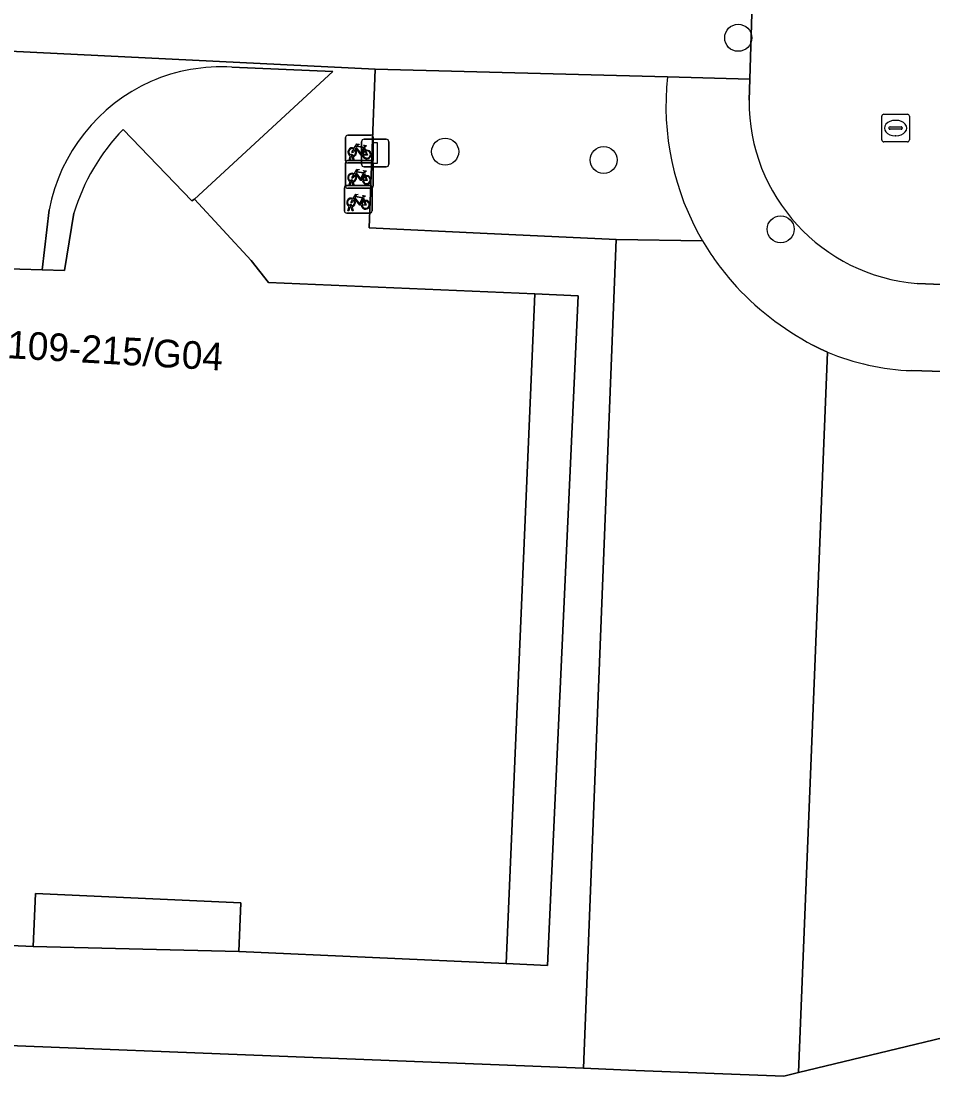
# Model space of a CAD drawing. Extents: x 161354 to 162026, y 386504 to 387460.
# Drawn here: x 161637.58 to 161670.51, y 386534.7 to 386573.47 of the extents above; entities that cross this region are included whole.
import ezdxf

# ---------------------------------------------------------------- set-up
doc = ezdxf.new("R2010")
doc.units = 0
for name, color, linetype in [('IMGEO_Boom', 7, 'Continuous'), ('IMGEO_Fietsenrek', 7, 'Continuous'), ('IMGEO_Groenvoorziening', 7, 'Continuous'), ('IMGEO_Haag', 7, 'Continuous'), ('IMGEO_Hek', 7, 'Continuous'), ('IMGEO_Lichtmast', 7, 'Continuous'), ('IMGEO_Pand', 7, 'Continuous'), ('IMGEO_Pand_nummerreeks', 7, 'Continuous'), ('IMGEO_Rijbaan_lokaal_open', 7, 'Continuous'), ('IMGEO_Rioolput', 7, 'Continuous'), ('IMGEO_Voetpad_open', 7, 'Continuous')]:
    doc.layers.add(name, color=color, linetype=linetype)

msp = doc.modelspace()

# ---------------------------------------------------------------- linework, layer by layer
at = {"layer": 'IMGEO_Boom'}
for centre in [(161663.488, 386572.878), (161652.895, 386568.761), (161658.624, 386568.459), (161665.024, 386565.954)]:
    msp.add_circle(centre, 0.489, dxfattribs=at)
at = {"layer": 'IMGEO_Fietsenrek'}
for p, q in [((161649.295, 386568.431), (161649.295, 386569.272)), ((161649.295, 386569.272), (161649.295, 386568.431)), ((161649.37, 386569.356), (161650.211, 386569.356)), ((161650.211, 386569.356), (161649.37, 386569.356)), ((161650.295, 386569.281), (161650.295, 386568.44)), ((161650.295, 386568.44), (161650.295, 386569.281)), ((161649.982, 386568.905), (161650.018, 386568.81)), ((161649.29, 386567.511), (161649.29, 386568.352)), ((161649.29, 386568.352), (161649.29, 386567.511)), ((161649.365, 386568.436), (161650.206, 386568.436)), ((161650.206, 386568.436), (161649.365, 386568.436)), ((161650.22, 386568.356), (161649.379, 386568.356)), ((161649.379, 386568.356), (161650.22, 386568.356)), ((161649.422, 386568.44), (161649.461, 386568.6)), ((161649.456, 386568.44), (161649.422, 386568.44)), ((161649.491, 386568.588), (161649.456, 386568.44)), ((161649.533, 386568.612), (161649.532, 386568.616)), ((161649.574, 386568.44), (161649.54, 386568.582)), ((161649.564, 386568.623), (161649.565, 386568.616)), ((161649.572, 386568.586), (161649.607, 386568.44)), ((161649.607, 386568.44), (161649.574, 386568.44)), ((161650.29, 386568.361), (161650.29, 386567.52)), ((161650.29, 386567.52), (161650.29, 386568.361)), ((161649.977, 386567.985), (161650.013, 386567.89)), ((161649.327, 386567.538), (161650.168, 386567.538)), ((161650.168, 386567.538), (161649.327, 386567.538)), ((161649.417, 386567.52), (161649.456, 386567.68)), ((161649.451, 386567.52), (161649.417, 386567.52)), ((161649.486, 386567.668), (161649.451, 386567.52)), ((161649.528, 386567.692), (161649.527, 386567.696)), ((161649.569, 386567.52), (161649.535, 386567.662)), ((161649.559, 386567.703), (161649.56, 386567.696)), ((161649.567, 386567.666), (161649.602, 386567.52)), ((161649.602, 386567.52), (161649.569, 386567.52)), ((161649.252, 386566.613), (161649.252, 386567.454)), ((161649.252, 386567.454), (161649.252, 386566.613)), ((161650.215, 386567.436), (161649.374, 386567.436)), ((161649.374, 386567.436), (161650.215, 386567.436)), ((161650.252, 386567.463), (161650.252, 386566.622)), ((161650.252, 386566.622), (161650.252, 386567.463)), ((161649.379, 386566.622), (161649.418, 386566.782)), ((161649.448, 386566.77), (161649.413, 386566.622)), ((161649.49, 386566.794), (161649.489, 386566.798)), ((161649.531, 386566.622), (161649.497, 386566.764)), ((161649.521, 386566.805), (161649.522, 386566.798)), ((161649.529, 386566.768), (161649.564, 386566.622)), ((161649.939, 386567.087), (161649.975, 386566.992)), ((161650.177, 386566.538), (161649.336, 386566.538)), ((161649.336, 386566.538), (161650.177, 386566.538)), ((161649.413, 386566.622), (161649.379, 386566.622)), ((161649.564, 386566.622), (161649.531, 386566.622))]:
    msp.add_line(p, q, dxfattribs=at)
for points in [[(161649.629, 386568.83), (161649.577, 386568.74), (161649.537, 386568.715), (161649.538, 386568.762), (161649.593, 386568.856)], [(161649.608, 386568.882), (161649.703, 386569.046), (161649.789, 386569.032), (161649.791, 386569.023), (161649.735, 386569.012), (161649.708, 386568.967), (161649.964, 386568.926)], [(161649.904, 386568.638), (161649.854, 386568.638), (161649.663, 386568.889), (161649.644, 386568.857)], [(161649.951, 386568.901), (161649.694, 386568.942), (161649.677, 386568.913), (161649.844, 386568.693), (161649.951, 386568.901)], [(161649.999, 386568.803), (161649.969, 386568.88), (161649.86, 386568.662), (161649.903, 386568.662)], [(161649.933, 386568.662), (161650.053, 386568.661), (161650.009, 386568.775)], [(161650.029, 386568.782), (161650.084, 386568.637), (161649.934, 386568.637)], [(161649.964, 386568.926), (161649.989, 386568.975), (161649.983, 386568.979), (161649.96, 386568.983), (161649.948, 386568.99), (161649.947, 386568.993), (161649.949, 386568.998), (161650.044, 386568.983), (161650.046, 386568.973), (161650.036, 386568.96), (161650.024, 386568.954), (161650.01, 386568.96), (161649.982, 386568.905)], [(161649.624, 386567.91), (161649.572, 386567.82), (161649.532, 386567.795), (161649.533, 386567.842), (161649.588, 386567.936)], [(161649.603, 386567.962), (161649.698, 386568.126), (161649.784, 386568.112), (161649.786, 386568.103), (161649.73, 386568.092), (161649.703, 386568.047), (161649.959, 386568.006)], [(161649.899, 386567.718), (161649.849, 386567.718), (161649.658, 386567.969), (161649.639, 386567.937)], [(161649.946, 386567.981), (161649.689, 386568.022), (161649.672, 386567.993), (161649.839, 386567.773), (161649.946, 386567.981)], [(161649.994, 386567.883), (161649.964, 386567.96), (161649.855, 386567.742), (161649.898, 386567.742)], [(161649.959, 386568.006), (161649.984, 386568.055), (161649.978, 386568.059), (161649.955, 386568.063), (161649.943, 386568.07), (161649.942, 386568.073), (161649.944, 386568.078), (161650.039, 386568.063), (161650.041, 386568.053), (161650.031, 386568.04), (161650.019, 386568.034), (161650.005, 386568.04), (161649.977, 386567.985)], [(161649.928, 386567.742), (161650.048, 386567.741), (161650.004, 386567.855)], [(161650.024, 386567.862), (161650.079, 386567.717), (161649.929, 386567.717)], [(161649.565, 386567.064), (161649.66, 386567.228), (161649.746, 386567.214), (161649.748, 386567.205), (161649.692, 386567.194), (161649.665, 386567.149), (161649.921, 386567.108)], [(161649.908, 386567.083), (161649.651, 386567.124), (161649.634, 386567.095), (161649.801, 386566.875), (161649.908, 386567.083)], [(161649.921, 386567.108), (161649.946, 386567.157), (161649.94, 386567.161), (161649.917, 386567.165), (161649.905, 386567.172), (161649.904, 386567.175), (161649.906, 386567.18), (161650.001, 386567.165), (161650.003, 386567.155), (161649.993, 386567.142), (161649.981, 386567.136), (161649.967, 386567.142), (161649.939, 386567.087)], [(161649.586, 386567.012), (161649.534, 386566.922), (161649.494, 386566.897), (161649.495, 386566.944), (161649.55, 386567.038)], [(161649.861, 386566.82), (161649.811, 386566.82), (161649.62, 386567.071), (161649.601, 386567.039)], [(161649.956, 386566.985), (161649.926, 386567.062), (161649.817, 386566.844), (161649.86, 386566.844)], [(161649.89, 386566.844), (161650.01, 386566.843), (161649.966, 386566.957)], [(161649.986, 386566.964), (161650.041, 386566.819), (161649.891, 386566.819)]]:
    msp.add_lwpolyline(points, dxfattribs=at)
for centre, radius, start, end in [((161649.373, 386569.278), 0.0779, 92.4484, 184.2845), ((161649.373, 386569.278), 0.0779, 92.4484, 184.2845), ((161650.217, 386569.278), 0.0779, 2.4484, 94.2845), ((161650.217, 386569.278), 0.0779, 2.4484, 94.2845), ((161649.535, 386568.741), 0.159, 62.6766, 242.1369), ((161649.535, 386568.741), 0.129, 63.3192, 238.903), ((161649.535, 386568.741), 0.129, 283.6043, 43.4302), ((161649.535, 386568.741), 0.159, 283.5766, 46.6042), ((161650.062, 386568.657), 0.159, 113.3408, 178.3217), ((161650.062, 386568.657), 0.159, 187.0065, 105.7708), ((161650.062, 386568.657), 0.129, 113.923, 177.9556), ((161650.062, 386568.657), 0.129, 188.6715, 104.5883), ((161649.368, 386568.358), 0.0779, 92.4484, 184.2845), ((161649.368, 386568.358), 0.0779, 92.4484, 184.2845), ((161649.373, 386568.434), 0.0779, 182.4484, 274.2845), ((161649.373, 386568.434), 0.0779, 182.4484, 274.2845), ((161649.515, 386568.612), 0.0499, 12.8025, 158.6934), ((161649.535, 386568.741), 0.159, 253.9967, 271.7867), ((161649.515, 386568.612), 0.0174, 12.8025, 163.4502), ((161649.535, 386568.741), 0.129, 253.415, 269.0204), ((161650.212, 386568.358), 0.0779, 2.4484, 94.2845), ((161650.212, 386568.358), 0.0779, 2.4484, 94.2845), ((161650.217, 386568.434), 0.0779, 272.4484, 4.2845), ((161650.217, 386568.434), 0.0779, 272.4484, 4.2845), ((161649.53, 386567.821), 0.159, 62.6766, 242.1369), ((161649.53, 386567.821), 0.129, 63.3192, 238.903), ((161649.53, 386567.821), 0.129, 283.6043, 43.4302), ((161649.53, 386567.821), 0.159, 283.5766, 46.6042), ((161650.057, 386567.737), 0.159, 187.0065, 105.7708), ((161649.33, 386567.46), 0.0779, 92.4484, 184.2845), ((161649.33, 386567.46), 0.0779, 92.4484, 184.2845), ((161649.368, 386567.514), 0.0779, 182.4484, 274.2845), ((161649.368, 386567.514), 0.0779, 182.4484, 274.2845), ((161649.51, 386567.692), 0.0499, 12.8025, 158.6934), ((161649.53, 386567.821), 0.159, 253.9967, 271.7867), ((161649.51, 386567.692), 0.0174, 12.8025, 163.4502), ((161649.53, 386567.821), 0.129, 253.415, 269.0204), ((161650.057, 386567.737), 0.159, 113.3408, 178.3217), ((161650.057, 386567.737), 0.129, 113.923, 177.9556), ((161650.057, 386567.737), 0.129, 188.6715, 104.5883), ((161650.174, 386567.46), 0.0779, 2.4484, 94.2845), ((161650.174, 386567.46), 0.0779, 2.4484, 94.2845), ((161650.212, 386567.514), 0.0779, 272.4484, 4.2845), ((161650.212, 386567.514), 0.0779, 272.4484, 4.2845), ((161649.492, 386566.923), 0.159, 62.6766, 242.1369), ((161649.492, 386566.923), 0.129, 63.3192, 238.903), ((161649.472, 386566.794), 0.0499, 12.8025, 158.6934), ((161649.492, 386566.923), 0.159, 253.9967, 271.7867), ((161649.472, 386566.794), 0.0174, 12.8025, 163.4502), ((161649.492, 386566.923), 0.129, 253.415, 269.0204), ((161649.492, 386566.923), 0.129, 283.6043, 43.4302), ((161649.492, 386566.923), 0.159, 283.5766, 46.6042), ((161650.019, 386566.839), 0.159, 113.3408, 178.3217), ((161650.019, 386566.839), 0.159, 187.0065, 105.7708), ((161650.019, 386566.839), 0.129, 113.923, 177.9556), ((161650.019, 386566.839), 0.129, 188.6715, 104.5883), ((161649.33, 386566.616), 0.0779, 182.4484, 274.2845), ((161649.33, 386566.616), 0.0779, 182.4484, 274.2845), ((161650.174, 386566.616), 0.0779, 272.4484, 4.2845), ((161650.174, 386566.616), 0.0779, 272.4484, 4.2845)]:
    msp.add_arc(centre, radius, start, end, dxfattribs=at)
at = {"layer": 'IMGEO_Groenvoorziening'}
for points in [[(161660.933, 386571.465), (161650.358, 386571.749), (161650.151, 386566.007), (161654.158, 386565.815), (161659.08, 386565.578), (161662.199, 386565.536)], [(161662.199, 386565.536), (161659.08, 386565.578), (161657.889, 386535.61), (161659.785, 386535.535), (161665.135, 386535.323), (161665.672, 386535.453), (161666.713, 386561.514)], [(161666.713, 386561.514), (161666.45, 386561.631), (161666.191, 386561.757)], [(161666.713, 386561.514), (161665.672, 386535.453), (161674.473, 386537.581), (161679.06, 386560.549)], [(161679.06, 386560.549), (161669.755, 386560.841)], [(161674.473, 386537.581), (161665.672, 386535.453), (161665.135, 386535.323), (161659.785, 386535.535), (161657.889, 386535.61), (161625.504, 386536.891), (161620.861, 386537.074), (161620.315, 386537.096), (161620.594, 386542.953), (161619.755, 386542.989), (161618.122, 386543.059), (161612.147, 386543.314), (161609.331, 386543.387), (161609.009, 386531.105), (161609.063, 386530.712), (161609.151, 386530.325), (161609.274, 386529.947), (161609.43, 386529.582), (161609.618, 386529.233), (161609.727, 386528.999), (161621.088, 386529.373), (161628.717, 386529.325)]]:
    msp.add_lwpolyline(points, dxfattribs=at)
for centre, radius, start, end in [((161670.543, 386570.417), 9.667, 173.7785, 210.3279), ((161670.625, 386570.475), 9.766, 210.3767, 221.1352), ((161671.1, 386571.021), 10.484, 221.6739, 242.081), ((161670.041, 386569.345), 8.509, 246.976, 268.0741)]:
    msp.add_arc(centre, radius, start, end, dxfattribs=at)
at = {"layer": 'IMGEO_Haag'}
msp.add_lwpolyline([(161660.933, 386571.465), (161650.358, 386571.749), (161650.151, 386566.007), (161654.158, 386565.815), (161659.08, 386565.578), (161662.199, 386565.536)], dxfattribs=at)
msp.add_arc((161670.543, 386570.417), 9.667, 173.7785, 210.3279, dxfattribs=at)
at = {"layer": 'IMGEO_Hek'}
for points in [[(161660.933, 386571.465), (161650.358, 386571.749)], [(161665.672, 386535.453), (161666.713, 386561.514)]]:
    msp.add_lwpolyline(points, dxfattribs=at)
for centre, radius, start, end in [((161670.543, 386570.417), 9.667, 173.7785, 210.3279), ((161670.625, 386570.475), 9.766, 210.3767, 221.1352), ((161671.1, 386571.021), 10.484, 221.6739, 242.081)]:
    msp.add_arc(centre, radius, start, end, dxfattribs=at)
at = {"layer": 'IMGEO_Lichtmast'}
for p, q in [((161649.868, 386568.312), (161649.868, 386569.112)), ((161649.868, 386569.112), (161649.868, 386568.312)), ((161649.968, 386569.212), (161650.758, 386569.212)), ((161650.758, 386569.212), (161649.968, 386569.212)), ((161650.858, 386569.112), (161650.858, 386568.312)), ((161650.858, 386568.312), (161650.858, 386569.112)), ((161650.758, 386568.212), (161649.968, 386568.212)), ((161649.968, 386568.212), (161650.758, 386568.212))]:
    msp.add_line(p, q, dxfattribs=at)
msp.add_lwpolyline([(161650.288, 386569.087), (161650.438, 386569.087), (161650.438, 386568.337), (161650.288, 386568.337), (161650.288, 386569.087)], dxfattribs=at)
for centre, start, end in [((161649.968, 386569.112), 90, 180), ((161649.968, 386569.112), 90, 180), ((161650.758, 386569.112), 0, 90), ((161650.758, 386569.112), 360, 90), ((161649.968, 386568.312), 180, 270), ((161649.968, 386568.312), 180, 270), ((161650.758, 386568.312), 270, 0), ((161650.758, 386568.312), 270, 0)]:
    msp.add_arc(centre, 0.1, start, end, dxfattribs=at)
at = {"layer": 'IMGEO_Pand'}
msp.add_lwpolyline([(161639.47, 386566.54), (161639.129, 386564.459), (161638.323, 386564.483), (161629.436, 386564.753), (161628.315, 386540.453), (161638.003, 386540.011), (161638.09, 386541.934), (161645.513, 386541.595), (161645.433, 386539.836), (161655.097, 386539.395), (161656.139, 386563.616), (161646.504, 386564.032), (161645.88, 386564.824), (161643.832, 386567.038), (161643.741, 386566.976), (161641.251, 386569.565)], dxfattribs=at)
msp.add_arc((161646.743, 386564.295), 7.612, 136.1811, 162.8432, dxfattribs=at)
at = {"layer": 'IMGEO_Rijbaan_lokaal_open'}
for points in [[(161666.593, 386638.288), (161666.283, 386630.519), (161664.774, 386592.69), (161664.775, 386592.396), (161664.044, 386574.981), (161664.002, 386574.56), (161663.903, 386571.385), (161663.879, 386570.626)], [(161669.958, 386563.994), (161749.766, 386560.739), (161782.705, 386559.514), (161784.324, 386559.563), (161785.513, 386559.811), (161786.674, 386560.164), (161787.8, 386560.619), (161788.881, 386561.173), (161789.907, 386561.821), (161790.022, 386561.902)]]:
    msp.add_lwpolyline(points, dxfattribs=at)
msp.add_arc((161670.491, 386570.584), 6.612, 179.6398, 265.3779, dxfattribs=at)
at = {"layer": 'IMGEO_Rioolput'}
for p, q in [((161668.677, 386569.187), (161668.677, 386570.039)), ((161668.752, 386570.113), (161669.604, 386570.113)), ((161669.165, 386569.893), (161669.19, 386569.893)), ((161669.678, 386570.039), (161669.678, 386569.187)), ((161668.936, 386569.607), (161668.936, 386569.619)), ((161669.374, 386569.57), (161668.976, 386569.57)), ((161668.979, 386569.656), (161669.377, 386569.656)), ((161669.42, 386569.619), (161669.42, 386569.607)), ((161669.604, 386569.113), (161668.752, 386569.113)), ((161669.188, 386569.333), (161669.163, 386569.333))]:
    msp.add_line(p, q, dxfattribs=at)
for points in [[(161668.677, 386569.187), (161668.677, 386570.039)], [(161668.752, 386570.113), (161669.604, 386570.113)], [(161669.678, 386570.039), (161669.678, 386569.187)], [(161669.604, 386569.113), (161668.752, 386569.113)]]:
    msp.add_lwpolyline(points, dxfattribs=at)
for centre, radius, start, end in [((161668.754, 386570.037), 0.0765, 91.552, 178.448), ((161668.754, 386570.037), 0.0765, 91.552, 178.448), ((161669.602, 386570.037), 0.0765, 1.552, 88.448), ((161669.602, 386570.037), 0.0765, 1.552, 88.448), ((161668.976, 386569.616), 0.0403, 85.8775, 175.7526), ((161668.973, 386569.606), 0.0366, 178.938, 274.7102), ((161669.377, 386569.613), 0.043, 264.8664, 352.4533), ((161669.381, 386569.618), 0.0386, 1.7309, 96.639), ((161668.754, 386569.189), 0.0765, 181.552, 268.448), ((161668.754, 386569.189), 0.0765, 181.552, 268.448), ((161669.602, 386569.189), 0.0765, 271.552, 358.448), ((161669.602, 386569.189), 0.0765, 271.552, 358.448)]:
    msp.add_arc(centre, radius, start, end, dxfattribs=at)
for centre, major_axis, ratio, start_param, end_param in [((161669.164, 386569.613), (-0.387, 0.002), 0.722429, 4.712389, 7.853982), ((161669.189, 386569.613), (-0.39, 0.002), 0.717154, 1.570796, 4.712389)]:
    msp.add_ellipse(centre, major_axis=major_axis, ratio=ratio, start_param=start_param, end_param=end_param, dxfattribs=at)
at = {"layer": 'IMGEO_Voetpad_open'}
for points in [[(161615.128, 386573.86), (161619.011, 386573.737), (161621.046, 386573.007), (161627.941, 386572.685), (161629.721, 386572.679), (161637.151, 386572.398), (161650.358, 386571.749), (161660.933, 386571.465), (161663.903, 386571.385), (161664.002, 386574.56)], [(161641.251, 386569.565), (161643.741, 386566.976), (161643.832, 386567.038), (161648.837, 386571.663), (161645.184, 386571.814)], [(161645.184, 386571.814), (161648.837, 386571.663), (161643.832, 386567.038), (161645.88, 386564.824), (161646.504, 386564.032), (161656.139, 386563.616)], [(161663.879, 386570.626), (161663.903, 386571.385), (161660.933, 386571.465)], [(161656.139, 386563.616), (161657.7, 386563.549), (161656.595, 386539.327), (161655.097, 386539.395), (161645.433, 386539.836), (161638.003, 386540.011), (161628.315, 386540.453), (161626.817, 386540.521), (161627.926, 386564.799), (161629.436, 386564.753), (161638.323, 386564.483), (161638.582, 386566.661)], [(161638.582, 386566.661), (161638.323, 386564.483), (161639.129, 386564.459), (161639.47, 386566.54)], [(161749.766, 386560.739), (161669.958, 386563.994)], [(161666.191, 386561.757), (161666.45, 386561.631), (161666.713, 386561.514)], [(161669.755, 386560.841), (161679.06, 386560.549), (161770.733, 386556.787), (161783.464, 386556.276)]]:
    msp.add_lwpolyline(points, dxfattribs=at)
for points in [[(161659.08, 386565.578), (161654.158, 386565.815), (161650.151, 386566.007), (161650.358, 386571.749), (161637.151, 386572.398), (161636.924, 386566.522), (161629.468, 386566.867), (161629.507, 386567.758), (161629.721, 386572.679), (161627.941, 386572.685), (161627.091, 386553.143), (161620.187, 386553.357), (161619.755, 386542.989), (161620.594, 386542.953), (161620.315, 386537.096), (161620.861, 386537.074), (161625.504, 386536.891), (161657.889, 386535.61)], [(161655.097, 386539.395), (161656.595, 386539.327), (161657.7, 386563.549), (161656.139, 386563.616)], [(161638.003, 386540.011), (161645.433, 386539.836), (161645.513, 386541.595), (161638.09, 386541.934)]]:
    msp.add_lwpolyline(points, close=True, dxfattribs=at)
for centre, radius, start, end in [((161644.8, 386565.41), 6.416, 86.5656, 113.3297), ((161644.8, 386565.41), 6.416, 86.5656, 113.3297), ((161670.543, 386570.417), 9.667, 173.7785, 210.3279), ((161644.863, 386565.461), 6.394, 114.0277, 169.1816), ((161644.863, 386565.461), 6.394, 114.0277, 169.1816), ((161670.491, 386570.584), 6.612, 179.6398, 265.3779), ((161646.743, 386564.295), 7.612, 136.1811, 162.8432), ((161670.625, 386570.475), 9.766, 210.3767, 221.1352), ((161671.1, 386571.021), 10.484, 221.6739, 242.081), ((161670.041, 386569.345), 8.509, 246.976, 268.0741)]:
    msp.add_arc(centre, radius, start, end, dxfattribs=at)

# ---------------------------------------------------------------- texts
at = {"layer": 'IMGEO_Pand_nummerreeks'}
msp.add_text('109-215/G04', height=1, rotation=356.6864, dxfattribs=at).set_placement((161637.039, 386561.294))

doc.saveas('drawing.dxf')
